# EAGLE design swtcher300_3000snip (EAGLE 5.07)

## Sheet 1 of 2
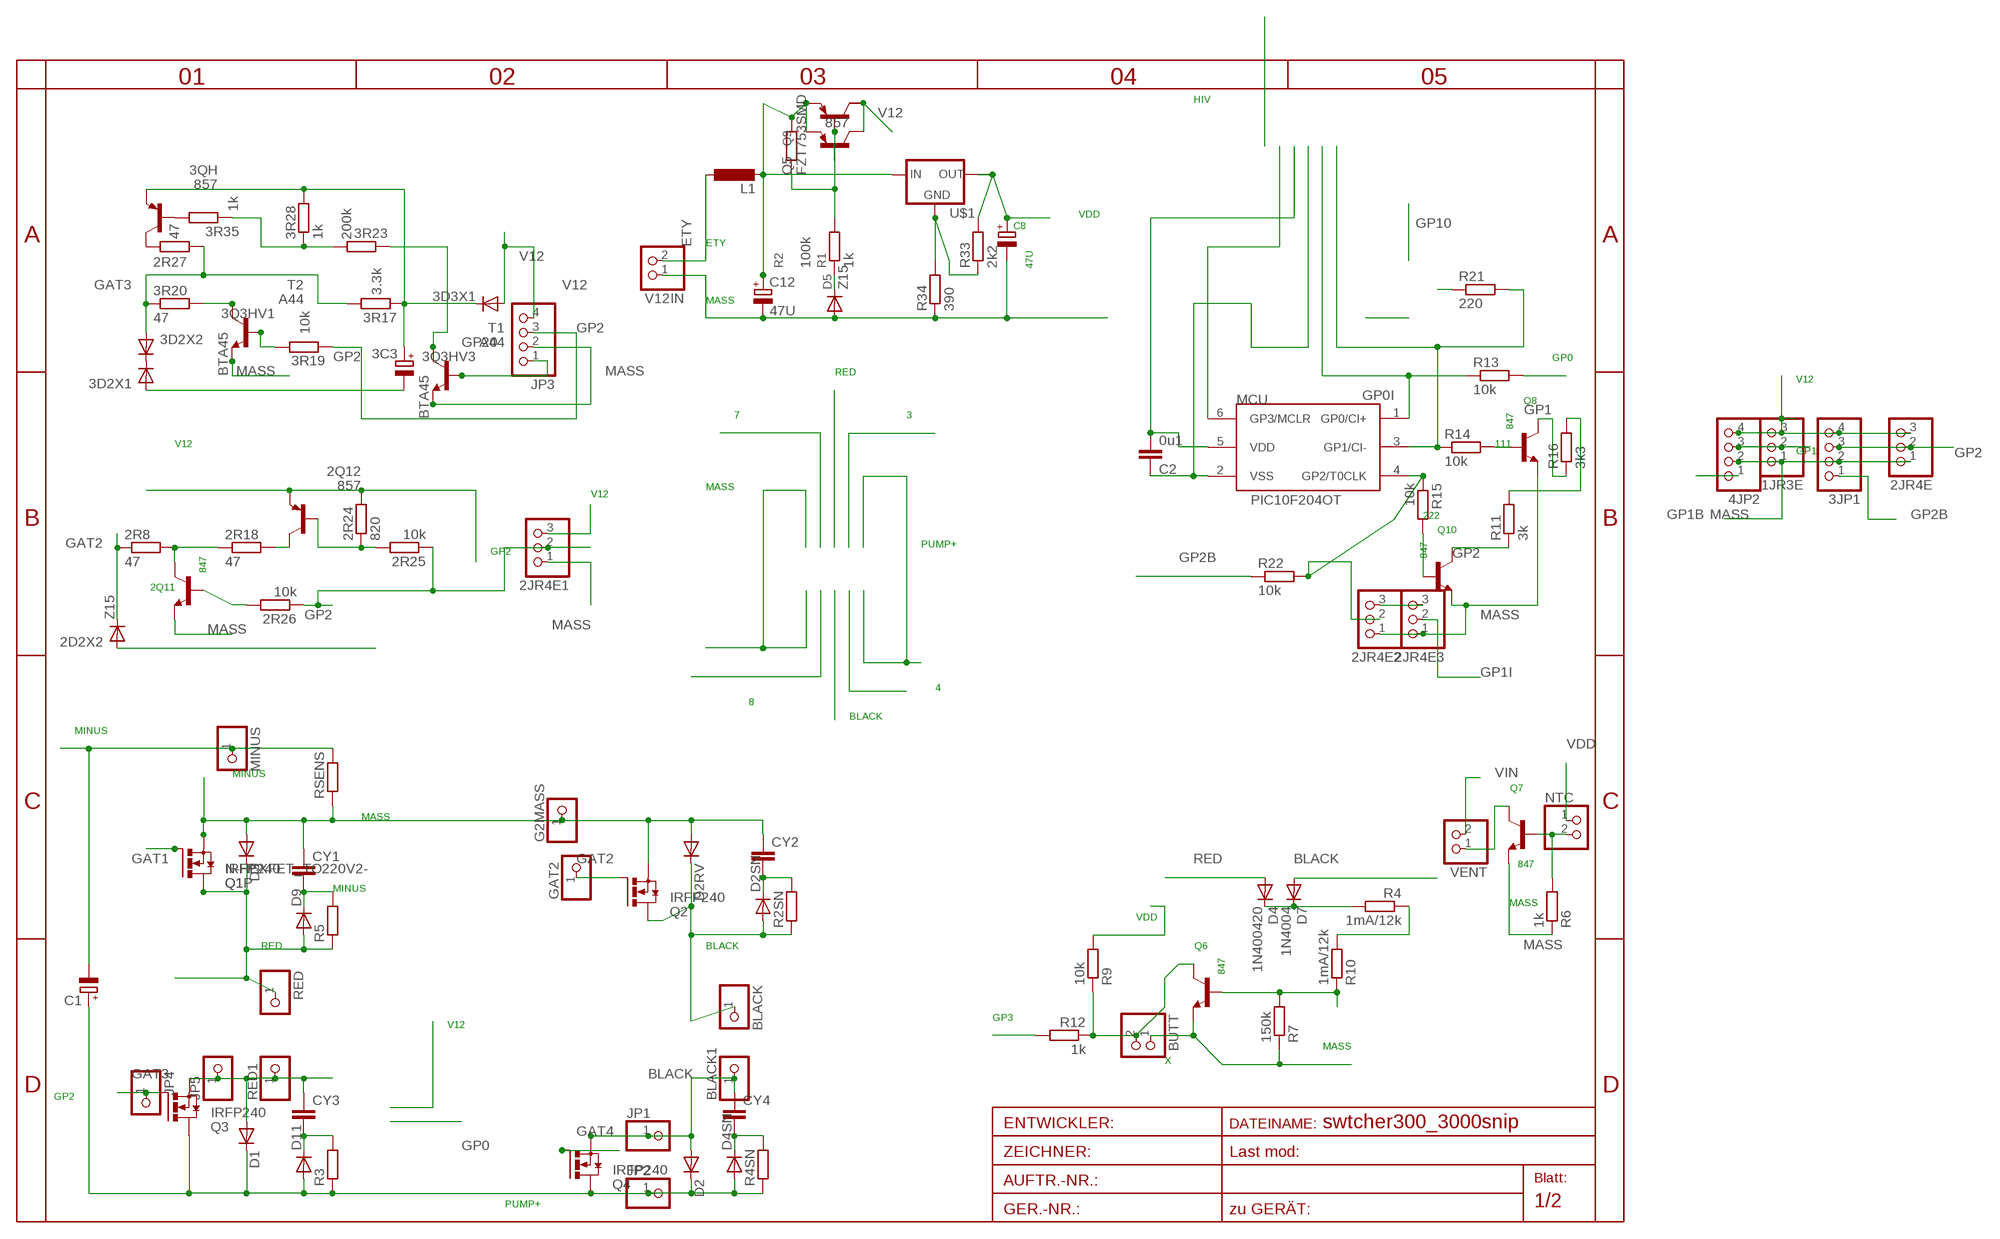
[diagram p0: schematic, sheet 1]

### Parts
1JR3E  PINHD-1X3  [1X03]
2D2X2  Z15  DIODE-MINIMELF  [MINIMELF]
2JR4E  PINHD-1X3  [1X03]
2JR4E1  PINHD-1X3  [1X03]
2JR4E2  PINHD-1X3  [1X03]
2JR4E3  PINHD-1X3  [1X03]
2Q11  847  BC847ALT1SMD  [SOT23]
2Q12  857  BC857ALT1SMD  [SOT23-BEC]
2R8  47  R-EU_R0805  [R0805]
2R18  47  R-EU_R0805  [R0805]
2R24  820  R-EU_R0805  [R0805]
2R25  10k  R-EU_R0805  [R0805]
2R26  10k  R-EU_R1206  [R1206]
2R27  47  R-EU_0207/10  [0207/10]
3C3  CPOL-EUD  [PANASONIC_D]
3D2X1  DIODE-MINIMELF  [MINIMELF]
3D2X2  DIODE-MINIMELF  [MINIMELF]
3D3X1  DIODE-SMA-DO214  [SMA-DO214AC]
3JP1  PINHD-1X4  [1X04]
3Q3HV1  BTA45  SMBTA45HV  [SOT23HV]
3Q3HV3  BTA45  SMBTA45HV  [SOT23HV]
3QH  857  BC857ALT1SMD  [SOT23-BEC]
3R17  3.3k  R-EU_R1206  [R1206]
3R19  10k  R-EU_R0805  [R0805]
3R20  47  R-EU_0207/12  [0207/12]
3R23  200k  R-EU_0204/2V  [0204V]
3R28  1k  R-EU_R0805  [R0805]
3R35  1k  R-EU_R0805  [R0805]
4JP2  PINHD-1X4  [1X04]
BLACK  PINHD-1X14.5MM  [1X4MM5]
BLACK1  PINHD-1X12MM3  [1X2MM3]
BUTT  PINHD-1X2STR  [1X02]
C1  CPOL-EUE5-13  [E5-13]
C2  0u1  C-EUC0805  [C0805]
C8  47U  CPOL-EUD  [PANASONIC_D]
C12  47U  CPOL-EUSMCA  [SMC_A]
CY1  CXXC10B6  [XC10B6]
CY2  CXXC10B6  [XC10B6]
CY3  CXXC22B7  [XC22B7]
CY4  CXXC10B5  [XC10B5]
D1  DIODE-SMC  [SMC]
D2  DIODE-SMC  [SMC]
D2RV  DIODE-SMC  [SMC]
D2SN  DIODE-SOD61E  [SOD61E]
D3  DIODE-SMC  [SMC]
D4  1N400420  [DO41-20]
D4SN  DIODE-P1-10  [P1-10]
D5  Z15  DIODE-MINIMELF  [MINIMELF]
D7  1N4004  [D-7.5]
D9  DIODE-SOD61E  [SOD61E]
D11  DIODE-D-12.5  [D-12.5]
G2MASS  PINHD-1X11MM0  [1X1MM0]
GAT2  PINHD-1X11MM0  [1X1MM0]
JP1  PINHD-1X11MM0  [1X1MM0]
JP2  PINHD-1X11MM0  [1X1MM0]
JP3  PINHD-1X4  [1X04]
JP4  PINHD-1X11MM0  [1X1MM0]
JP5  PINHD-1X11MM0  [1X1MM0]
L1  L-EU0204/5  [0204/5]
MCU  PIC10F204OT  [SOT23-6]
MINUS  PINHD-1X14.5MM  [1X4MM5]
NTC  PINHD-1X2STR  [1X02]
Q1  IRFP240  [TO247BV]
Q1P  N-HEXFET_TO220V2-  [TO220BV2]
Q2  IRFP240  [TO247BV]
Q3  IRFP240  [TO247BV]
Q4  IRFP240  [TO247BV]
Q5  FZT753SMD  [SOT223]
Q6  847  BC847ALT1SMD  [SOT23]
Q7  847  BC847ALT1SMD  [SOT23]
Q8  847  BC847ALT1SMD  [SOT23]
Q9  857  BC857ALT1SMD  [SOT23-BEC]
Q10  847  BC847ALT1SMD  [SOT23]
R1  1k  R-EU_R0805  [R0805]
R2  100k  R-EU_R0805  [R0805]
R2SN  R-EU_0617/22  [0617/22]
R3  R-EU_0617/17  [0617/17]
R4  1mA/12k  R-EU_R1210  [R1210]
R4SN  R-EU_0207/10  [0207/10]
R5  R-EU_0617/22  [0617/22]
R6  1k  R-EU_R0805  [R0805]
R7  150k  R-EU_R0805  [R0805]
R9  10k  R-EU_R0805  [R0805]
R10  1mA/12k  R-EU_R1210  [R1210]
R11  3k  R-EU_R1206  [R1206]
R12  1k  R-EU_R0805  [R0805]
R13  10k  R-EU_R0805  [R0805]
R14  10k  R-EU_R0805  [R0805]
R15  10k  R-EU_R0805  [R0805]
R16  3k3  R-EU_R0805  [R0805]
R21  220  R-EU_R0805  [R0805]
R22  10k  R-EU_R1206  [R1206]
R33  2k2  R-EU_R0805  [R0805]
R34  390  R-EU_R0805  [R0805]
RED  PINHD-1X14.5MM  [1X4MM5]
RED1  PINHD-1X12MM3  [1X2MM3]
RSENS  R-EU_CERAM35  [CERAM35]
T1  A44  2N2222-NPN-TO92-EBC  [TO92-EBC]
T2  A44  2N2222-NPN-TO92-EBC  [TO92-EBC]
U$1  AP1117  [SOT223]
V12IN  PINHD-1X2STR  [1X02]
VENT  PINHD-1X2STR  [1X02]

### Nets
111: Q8.1(B) R14.2
222: Q10.1(B) R15.2
BLACK: BLACK1.1 BLACK.1 CY4.1 D2.A D2RV.C D2SN.A D7.A JP1.1 Q2.D Q4.S R2SN.1
BTRAP+: 3C3.+ 3D3X1.K(C) 3QH.E 3R17.1 3R28.2
ETY: L1.1 V12IN.2
GAT1: Q1.G Q1P.G
GAT2: 2D2X2.C 2R8.1 GAT2.1 Q2.G
GAT3: 2R27.2 3D2X2.A 3R17.2 3R20.1 JP4.1 Q3.G
GAT4: Q4.G
GP0: R13.2
GP0I: MCU.1(GP0/CI+) R13.1 ; also sheet 2
GP1: 1JR3E.2 4JP2.3 Q8.3(C) R16.1
GP1B: 4JP2.1 R21.1
GP1I: 2JR4E3.2 MCU.3(GP1/CI-) R14.1 R21.2 ; also sheet 2
GP2: 2JR4E1.2 2JR4E.2 2R25.1 2R26.1 3JP1.3 3R19.1 JP3.3 Q10.3(C) R11.1
GP2B: 3JP1.1 3Q3HV3.1(B) JP3.1 R22.1 T1.B
GP2I: 2JR4E2.2 MCU.4(GP2/T0CLK) R15.1 R22.2 ; also sheet 2
GP3: MCU.6(GP3/MCLR) R12.2 ; also sheet 2
GP20: 3Q3HV3.3(C) 3R23.2 T1.C
HVC1: 3Q3HV1.3(C) 3R20.2 T2.C
MASS: 1JR3E.1 2D2X2.A 2JR4E1.1 2JR4E2.1 2JR4E3.1 2JR4E.1 2Q11.2(E) 3JP1.2 3Q3HV1.2(E) 3Q3HV3.2(E) 4JP2.2 BUTT.1 C2.1 C8.- C12.- CY1.1 CY2.1 D2RV.A D3.A D5.A G2MASS.1 JP3.2 MCU.2(VSS) Q1.S Q1P.S Q2.S Q6.2(E) Q7.2(E) Q8.2(E) Q10.2(E) R6.1 R7.1 R34.1 RSENS.1 T1.E T2.E V12IN.1 ; also sheet 2
MINUS: C1.- MINUS.1 RSENS.2
N$1: D4.C D7.C R4.2
N$2: Q5.1(B) Q9.B R1.2 R2.1
N$3: D5.C R1.1
N$4: 2Q11.3(C) 2R8.2 2R18.1
N$5: Q6.1(B) R7.2 R10.1
N$6: 2Q12.B 2R24.1 2R25.2
N$7: R4.1 R10.2
N$8: 2Q12.C 2R18.2
N$9: NTC.2 Q7.1(B) R6.2
N$10: Q7.3(C) VENT.1
N$12: 3Q3HV1.1(B) 3R19.2 T2.B
N$13: 2R27.1 3QH.C
N$17: 3QH.B 3R35.2
N$18: 3R23.1 3R28.1 3R35.1
N$21: 3D2X1.C 3D2X2.C
N$22: 2Q11.1(B) 2R26.2
N$30: R33.1 R34.2 U$1.1(GND)
PUMP+: C1.+ D1.C D2.C D4SN.A D11.A JP2.1 Q3.D Q4.D R3.1 R4SN.1 ; also sheet 2
RED: 3C3.- 3D2X1.A CY3.1 D1.A D3.C D4.A D9.A JP5.1 Q1.D Q1P.D Q3.S R5.1 RED1.1 RED.1
SNUB1: CY3.2 D11.C R3.2
SNUB2: CY4.2 D4SN.C R4SN.2
SNUB3: CY2.2 D2SN.C R2SN.2
SNUB4: CY1.2 D9.C R5.2
V12: 1JR3E.3 2JR4E1.3 2JR4E2.3 2JR4E3.3 2JR4E.3 2Q12.E 2R24.2 3D3X1.A 3JP1.4 4JP2.4 JP3.4 Q5.2(C) Q9.C R11.2 R16.2
VDD: C2.2 C8.+ MCU.5(VDD) NTC.1 R9.2 R33.2 U$1.2(OUT) U$1.4(TAB) ; also sheet 2
VIN: C12.+ L1.2 Q5.3(E) Q9.E R2.2 U$1.3(IN) VENT.2
X: BUTT.2 Q6.3(C) R9.1 R12.1
Unconnected: Q5.4(C/)

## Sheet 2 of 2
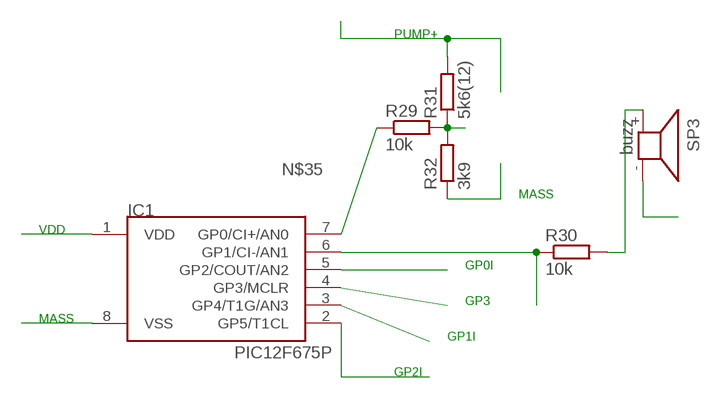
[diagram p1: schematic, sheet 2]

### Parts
IC1  PIC12F675P  [DIL8]
R29  10k  R-EU_R0805  [R0805]
R30  10k  R-EU_R0805  [R0805]
R31  5k6(12)  R-EU_0207/30  [0207/30]
R32  3k9  R-EU_R0805  [R0805]
SP3  buzz  KSS12017MM  [KSS1202]

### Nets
GP0I: IC1.5(GP2/COUT/AN2) ; also sheet 1
GP1I: IC1.3(GP4/T1G/AN3) ; also sheet 1
GP2I: IC1.2(GP5/T1CL) ; also sheet 1
GP3: IC1.4(GP3/MCLR) ; also sheet 1
MASS: IC1.8(VSS) R32.1 SP3.- ; also sheet 1
N$24: R30.2 SP3.+
N$31: IC1.6(GP1/CI-/AN1) R30.1
N$34: R29.2 R31.1 R32.2
N$35: IC1.7(GP0/CI+/AN0) R29.1
PUMP+: R31.2 ; also sheet 1
VDD: IC1.1(VDD) ; also sheet 1

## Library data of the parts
1JR3E 2JR4E 2JR4E1-2JR4E3 = pinhead:PINHD-1X3: PIN HEADER
2D2X2 3D2X1 3D2X2 3D3X1 D1 D2 D2RV D2SN D3 D4SN D5 D9 D11 = diode:DIODE-: DIODE
2Q11 Q6-Q8 Q10 = transistor-npn:BC847*: NPN Transistor
2Q12 3QH Q9 = transistor-pnp:BC857*: PNP Transistror
2R8 2R18 2R24-2R27 3R17 3R19 3R20 3R23 3R28 3R35 R2SN R4 R4SN R5-R7 R9 R10 R12 RSENS = rcl:R-EU_: RESISTOR, European symbol
3C3 C1 = rcl:CPOL-EU: POLARIZED CAPACITOR, European symbol
3JP1 4JP2 JP3 = pinhead:PINHD-1X4: PIN HEADER
3Q3HV1 3Q3HV3 = transistor-npn:SMBTA45
BLACK BLACK1 G2MASS GAT2 JP1 JP2 JP4 JP5 MINUS RED RED1 = pinhead:PINHD-1X1: PIN HEADER
BUTT NTC V12IN VENT = pinhead:PINHD-1X2: PIN HEADER
C2 = rcl:C-EU: CAPACITOR, European symbol
C8 C12 = rcl-2:CPOL-EU: POLARIZED CAPACITOR, European symbol
CY1-CY4 = rcl:CX: X CAPACITOR
D4 D7 = diode:1N4004: DIODE
IC1 = microchip-5:PIC12F6*: uPC nW 1k Program Flash memory 2x Timer Comparator 10b A/D converter/ 4xIN
L1 = rcl:L-EU: INDUCTOR, European symbol
MCU = microchip-3:PIC10F2*: uPC nW 0,25/0,5k Program Flash memory Comparator
Q1-Q4 = transistor-power:IRFP240: HEXFET Power MosFet Source: http://www.irf.com/
Q1P = transistor-power:N-HEXFET_?-*: HEXFET® Power MOSFET
Q5 = transistor-pnp:FZT753SMD: PNP Transistor
R1-R3 R11 R13-R16 R21 R22 R29-R34 = rcl-2:R-EU_: RESISTOR, European symbol
SP3 = buzzer:KSS1201: SPEAKER
T1 T2 = transistor-neu-to92:*-NPN-: NPN Transistror
U$1 = v-reg:AP1117

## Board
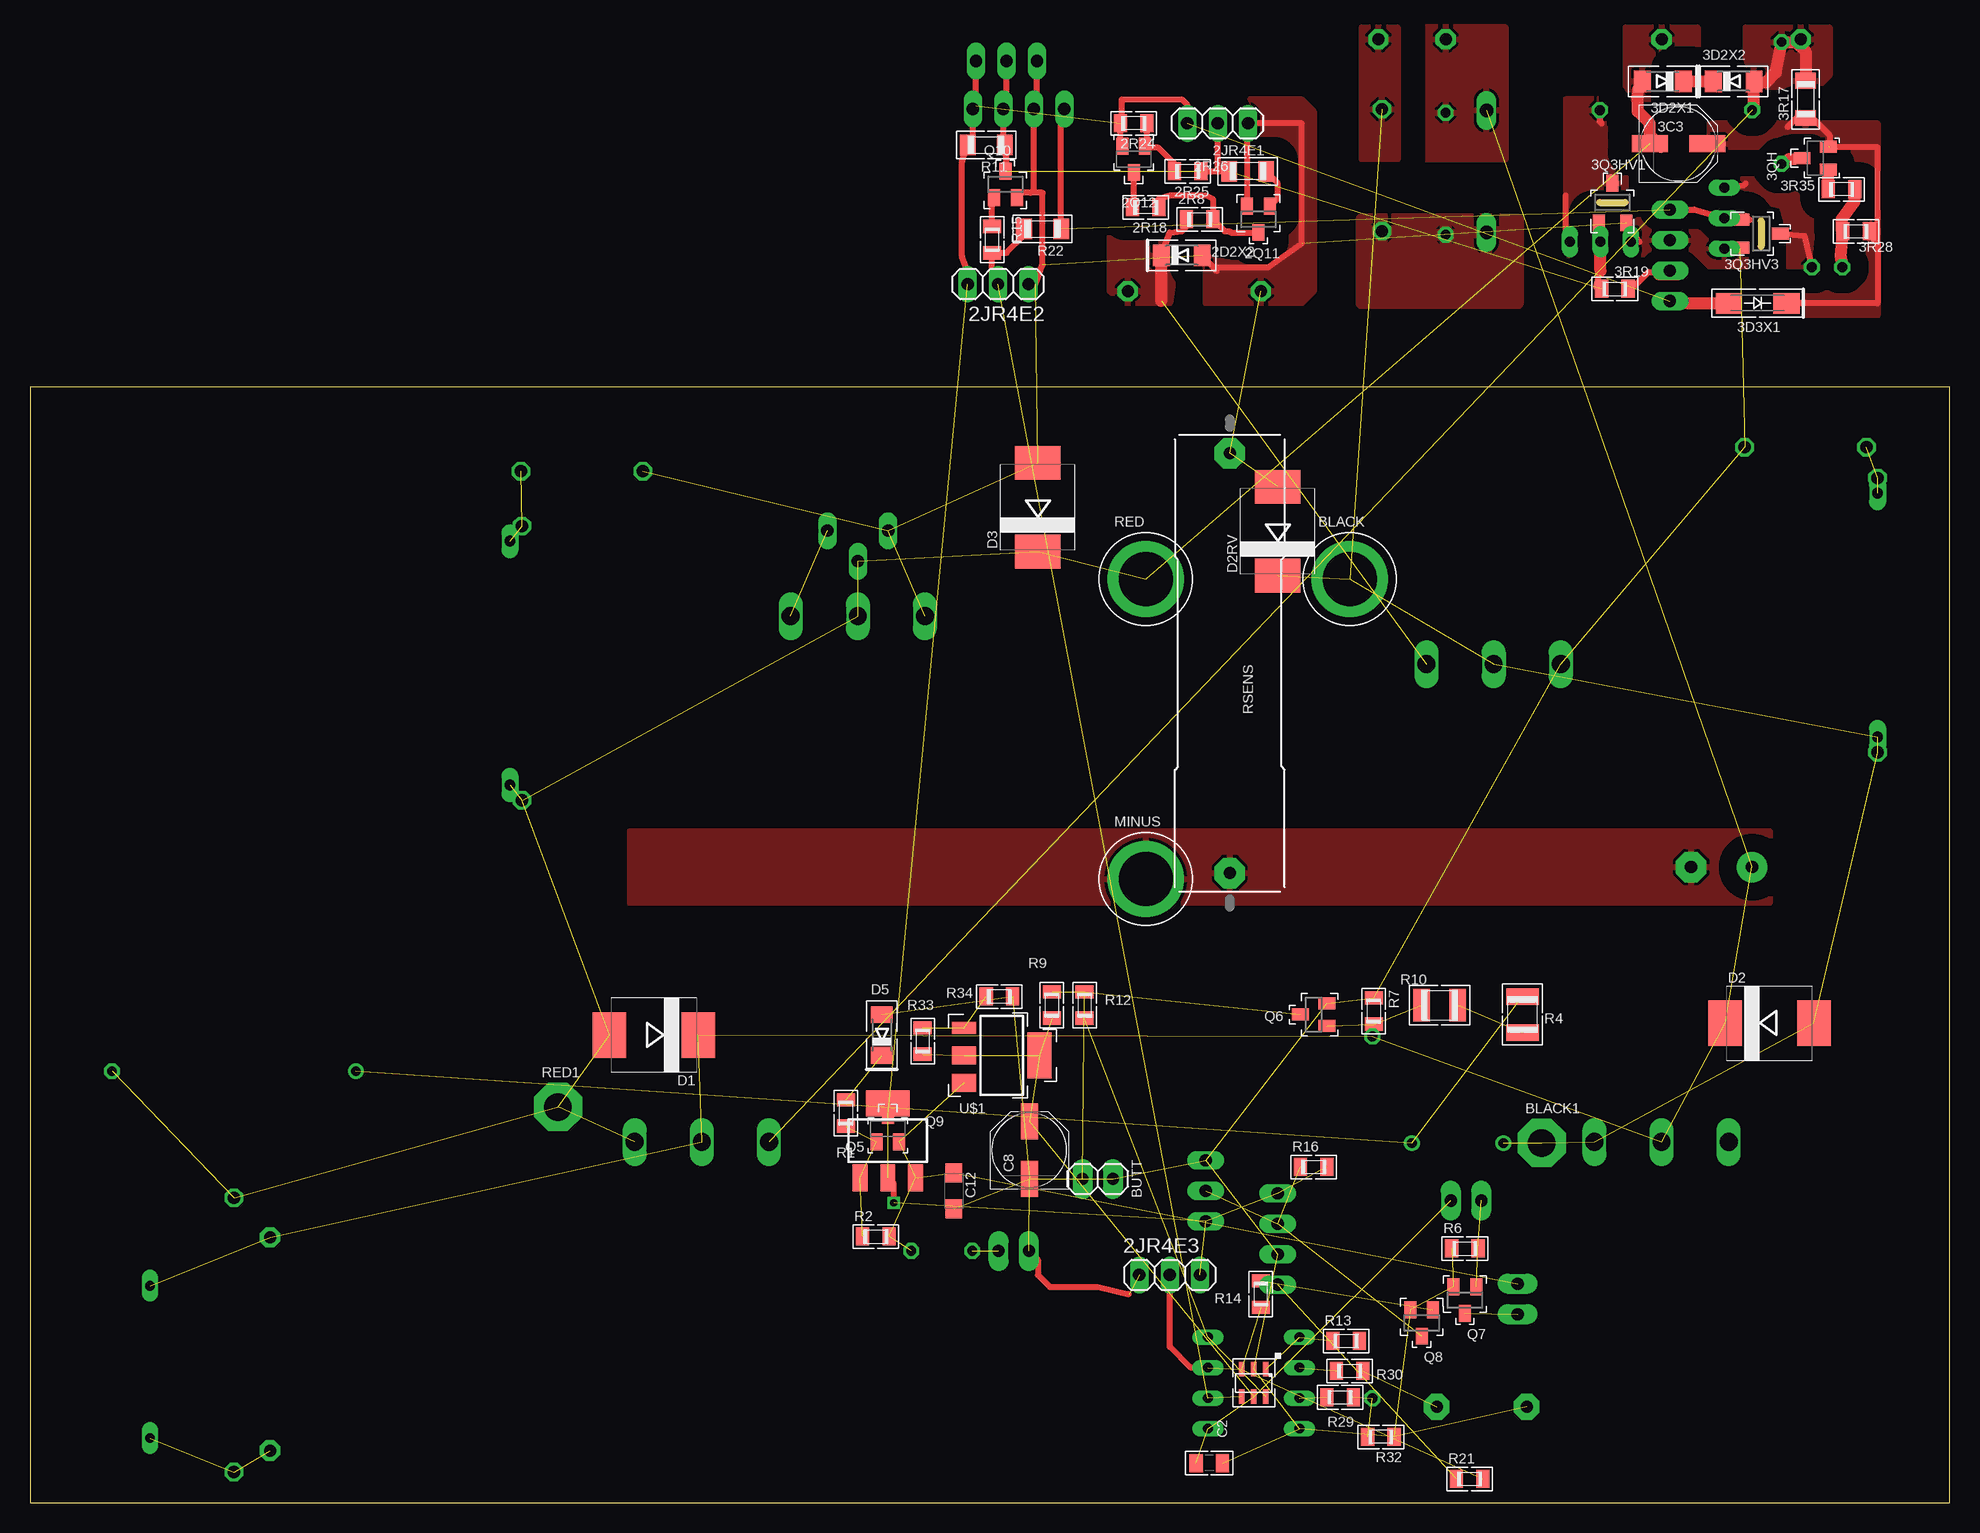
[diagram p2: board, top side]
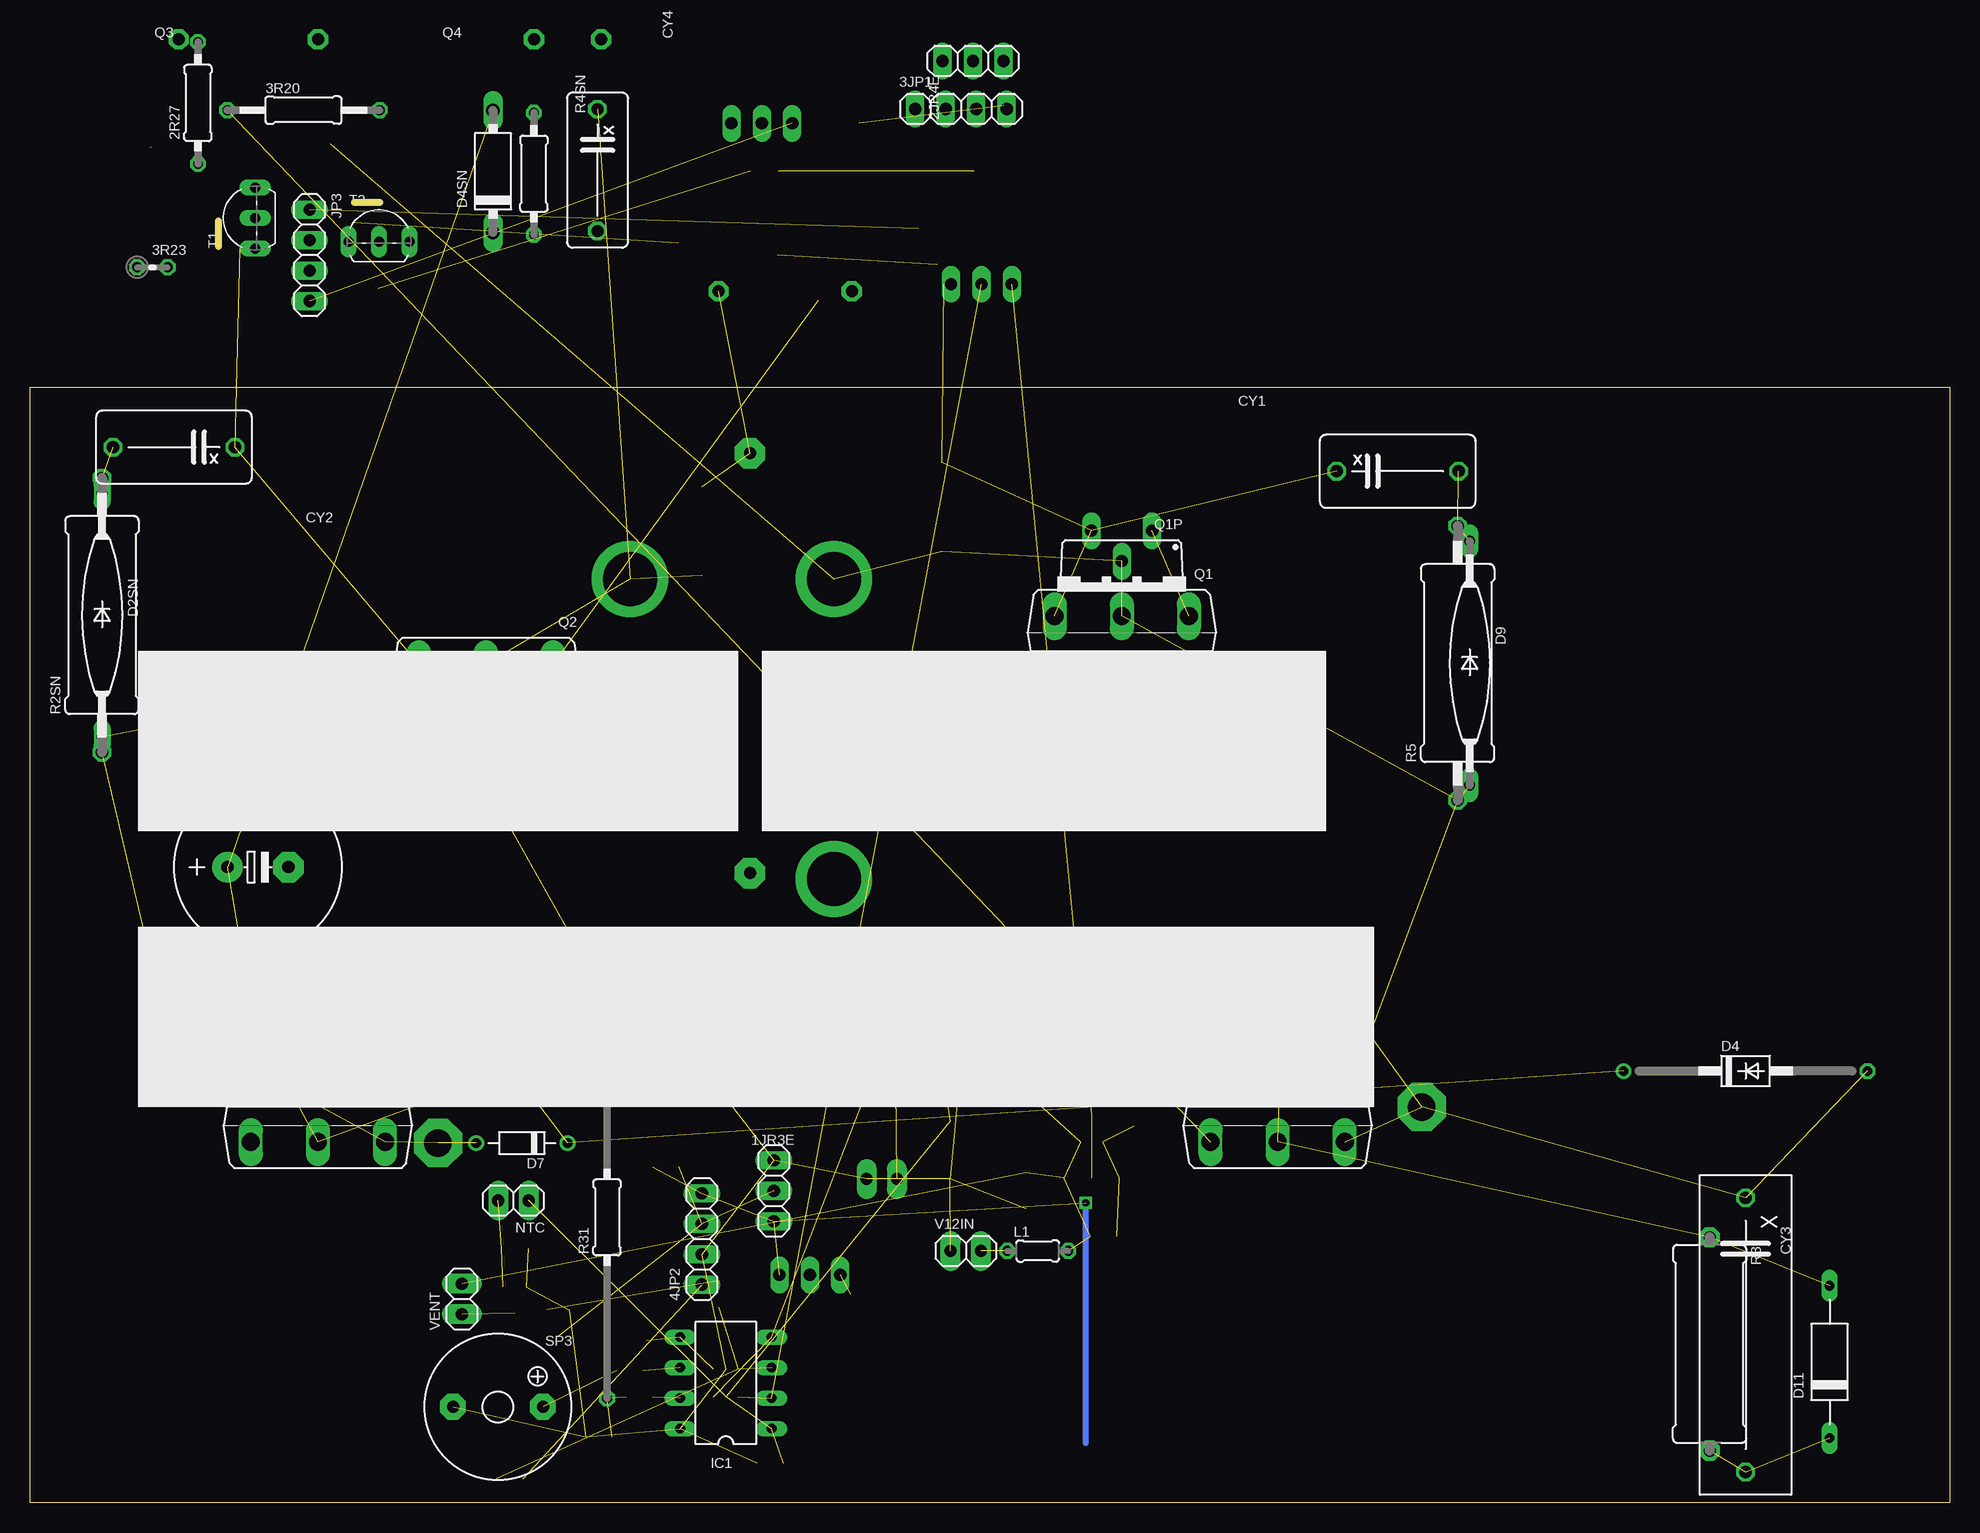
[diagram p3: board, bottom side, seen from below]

Size 160 x 93 mm. Coordinates in mm from the lower left corner, seen from the top.
Outline: 0,0 160,0 160,93 0,93 0,0
Copper layers (1*16): Top 0.035mm / dielectric 1.5mm / Bottom 0.035mm
Design rules "default *": minimum track width 10mil, minimum drill 20mil, track to track 8mil, track to pad 8mil, pad to pad 8mil, via to via 8mil, smd to smd 8mil, copper to edge 40mil, drill to drill 8mil, minimum pad ring 10mil, minimum via ring 8mil, stop-mask expansion 4mil, vias tented up to drill 0mil, thermal gap 10mil

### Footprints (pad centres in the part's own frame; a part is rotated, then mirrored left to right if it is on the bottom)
1X03 = drill 1.016 long: 1 -2.54,0; 2 0,0; 3 2.54,0
MINIMELF = smd 1.4 x 1.8: A 1.7,0; C -1.7,0
SOT23 = smd 1 x 1.4: 1 -0.95,-1.1; 2 0.95,-1.1; 3 0,1.1
SOT23-BEC = smd 1 x 1.4: B -0.95,-1.1; C 0,1.1; E 0.95,-1.1
R0805 = smd 1.1 x 1.5: 1 -1.1,0; 2 1.1,0
R1206 = smd 1.3 x 1.7: 1 -1.55,0; 2 1.55,0
0207/10 = drill 0.813 octagon: 1 -5.08,0; 2 5.08,0
PANASONIC_D = smd 3 x 1.4: + 2.4,0; - -2.4,0
SMA-DO214AC = smd 2.2 x 1.7: A 2.4,0; K -2.4,0
1X04 = drill 1.016 long: 1 -3.81,0; 2 -1.27,0; 3 1.27,0; 4 3.81,0
SOT23HV = smd 1 x 1.4: 1 -1.15,-1.7; 2 1.15,-1.7; 3 0,1.6
0207/12 = drill 0.813 octagon: 1 -6.35,0; 2 6.35,0
0204V = drill 0.813 octagon: 1 -1.27,0; 2 1.27,0
1X4MM5 = drill 4.5 pad 6.35 round: 1 0,0
1X2MM3 = drill 2.3 pad 4 octagon: 1 0,0
1X02 = drill 1.016 pad 1.676 long: 1 -1.27,0; 2 1.27,0
E5-13 = drill 1.016 pad 2.54 round: + -2.54,0 | drill 1.016 pad 2.54 octagon: - 2.54,0
C0805 = smd 1.1 x 1.5: 1 -1.1,0; 2 1.1,0
SMC_A = smd 1.6 x 1.4: + -1.5,0; - 1.5,0
XC10B6 = drill 1.016 octagon: 1 -5.08,0; 2 5.08,0
XC22B7 = drill 1.016 octagon: 1 -11.43,0; 2 11.43,0
XC10B5 = drill 1.016 octagon: 1 -5.08,0; 2 5.08,0
SMC = smd 2.8 x 3.8: A 3.7,0; C -3.7,0
SOD61E = drill 0.914 long: A 10.16,0; C -10.16,0
DO41-20 = drill 0.8 octagon: A 10.16,0 | drill 0.8 round: C -10.16,0
P1-10 = drill 1.118 long: A 5.08,0; C -5.08,0
D-7.5 = drill 0.8 round: A 3.81,0; C -3.81,0
D-12.5 = drill 0.813 long: A 6.35,0; C -6.35,0
1X1MM0 = drill 1 pad 1.676 octagon: 1 0,0
DIL8 = drill 0.8 long: 1 -3.81,-3.81; 2 -1.27,-3.81; 3 1.27,-3.81; 4 3.81,-3.81; 5 3.81,3.81; 6 1.27,3.81; 7 -1.27,3.81; 8 -3.81,3.81
0204/5 = drill 0.813 octagon: 1 -2.54,0; 2 2.54,0
SOT23-6 = smd 0.45 x 1.2: 1 -1.016,-1.15; 2 0,-1.15; 3 1.016,-1.15; 4 1.016,1.15; 5 0,1.15; 6 -1.016,1.15
TO247BV = drill 1.499 long: D 0,-2.921; G -5.588,-2.921; S 5.588,-2.921
TO220BV2 = drill 1.016 long: D 0,0; G -2.54,-2.54; S 2.54,-2.54
SOT223 = smd 1.219 x 2.235: 1 -2.311,-3.099; 2 0,-3.099; 3 2.311,-3.099 | smd 3.6 x 2.2: 4 0,3.099
0617/22 = drill 1.016 octagon: 1 -11.43,0; 2 11.43,0
0617/17 = drill 1 pad 1.676 octagon: 1 -8.89,0; 2 8.89,0
R1210 = smd 1.4 x 2.7: 1 -1.5,0; 2 1.5,0
0207/30 = drill 0.813 octagon: 1 -15.08,0; 2 15.08,0
CERAM35 = drill 1 pad 2.54 octagon: 1 -17.5,0; 2 17.5,0
KSS1202 = drill 1 pad 2.159 octagon: + 3.75,0; - -3.75,0
TO92-EBC = drill 0.813 long: B 0,-1.27; C 2.54,-1.27; E -2.54,-1.27
SOT223' = smd 1 x 2: 1 -2.3,-3.15 | smd 1.5 x 2: 2 0,-3.15; 3 2.3,-3.15 | smd 3.8 x 2: 4 0,3.15

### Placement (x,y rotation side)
1JR3E  98,26 270 bottom
2D2X2  96,104 0 top  (outside the outline)
2JR4E  81.4,120.2 0 bottom  (outside the outline)
2JR4E1  99,115 180 top  (outside the outline)
2JR4E2  80.7,101.6 180 top  (outside the outline)
2JR4E3  95,19 0 top
2Q11  102.4,107 180 top  (outside the outline)
2Q12  92,112 180 top  (outside the outline)
2R8  97.5,107 0 top  (outside the outline)
2R18  93,108 180 top  (outside the outline)
2R24  92,115 180 top  (outside the outline)
2R25  96.5,111 180 top  (outside the outline)
2R26  101.5,111 0 top  (outside the outline)
2R27  146,116.7 90 bottom  (outside the outline)
3C3  137.4,113.3 0 top  (outside the outline)
3D2X1  136.1,118.5 180 top  (outside the outline)
3D2X2  142,118.5 0 top  (outside the outline)
3D3X1  144,100 180 top  (outside the outline)
3JP1  82.4,116.2 0 bottom  (outside the outline)
3Q3HV1  131.9,108.4 0 top  (outside the outline)
3Q3HV3  144.3,105.8 270 top  (outside the outline)
3QH  148.8,112.1 90 top  (outside the outline)
3R17  148,117 90 top  (outside the outline)
3R19  not placed on the board
3R20  137.2,116.1 0 bottom  (outside the outline)
3R23  149.8,103 0 bottom  (outside the outline)
3R28  152.2,106 0 top  (outside the outline)
3R35  151,109.5 180 top  (outside the outline)
4JP2  104,22 90 bottom
BLACK  110,77 0 top
BLACK1  126,30 0 top
BUTT  89,27 180 top
C1  141,53 0 bottom
C2  98.3,3.32 180 top
C8  83.3,29.4 90 top
C12  77,26 270 top
CY1  46,86 0 bottom
CY2  148,88 180 bottom
CY3  17,14 270 bottom
CY4  not placed on the board
D1  52,39 180 top
D2  145,40 0 top
D2RV  104,81 90 top
D2SN  154,74 270 bottom
D3  84,83 90 top
D4  17,36 0 bottom
D4SN  not placed on the board
D5  71,39 90 top
D7  119,30 180 bottom
D9  40,70 270 bottom
D11  10,11.75 90 bottom
G2MASS  not placed on the board
GAT2  not placed on the board
IC1  102,10 90 bottom
JP1  not placed on the board
JP2  not placed on the board
JP3  136.7,104 270 bottom  (outside the outline)
JP4  147.6,122 0 top  (outside the outline)
JP5  not placed on the board
L1  76,21 0 bottom
MCU  102,10 180 top
MINUS  93,52 0 top
NTC  119.7,25.2 180 bottom
Q1  69,71 180 bottom
Q1P  69,78.5 180 bottom
Q2  122,67 180 bottom
Q3  56,33 0 bottom
Q4  136,33 0 bottom
Q5  71.5,30.2 0 top
Q6  107,40.7 90 top
Q7  119.6,16.9 180 top
Q8  116,15 180 top
Q9  71.5,31.2 0 top
Q10  81.3,109.9 0 top  (outside the outline)
R1  68,32.5 270 top
R2  70.5,22.2 0 top
R2SN  154,74 90 bottom
R3  20,13.25 270 bottom
R4  124.4,40.7 90 top
R4SN  not placed on the board
R5  41,70 90 bottom
R6  119.6,21.2 0 top
R7  112,41 270 top
R9  85.17,41.5 270 top
R10  117.5,41.5 0 top
R11  79.7,113.2 180 top  (outside the outline)
R12  87.9,41.5 270 top
R13  109.7,13.5 0 top
R14  102.6,17.4 90 top
R15  80.2,105.3 90 top  (outside the outline)
R16  107,28 0 top
R21  120,2 0 top
R22  84.4,106.2 180 top  (outside the outline)
R29  109.2,8.8 0 top
R30  110,11 0 top
R31  111.9,23.8 90 bottom
R32  112.6,5.5 180 top
R33  74.4,38.5 270 top
R34  80.8,42.2 180 top
RED  93,77 0 top
RED1  44,33 0 top
RSENS  100,70 270 top
SP3  121,8 0 bottom
T1  142.5,107.1 90 bottom  (outside the outline)
T2  130.9,106.4 0 bottom  (outside the outline)
U$1  AP1117  [SOT223']  81,37.3 270 top
V12IN  82,21 0 bottom
VENT  124,17 90 bottom

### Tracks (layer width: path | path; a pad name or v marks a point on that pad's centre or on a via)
111  (1 unrouted)
222
  Top 0.5: R15.2 80.2,108.85 Q10.1
BLACK  (9 unrouted)
  pour Top (isolate 2): 111,123 114,123 114,112 111,112
BTRAP+  (1 unrouted)
  Top 0.5: 3R28.2 153.3,105.7 154,105 | 154,105 154,113 150.25,113 3QH.E | 150,113 150,114 148.55,115.45 3R17.1 147.25,115.45 146.5,114.7 | 154,105 154,100 3D3X1.K
  pour Top (isolate 1.5): 140,115 154,115 154,99 147,99 147,101 152,101 152,113 140,113
ETY  (1 unrouted)
GAT1  (1 unrouted)
GAT2  (1 unrouted)
  Top 0.5: 2R8.1 96.7,106.7 96,106 95,105.9 2D2X2.C
  Top 1: 94.3,100.2 2D2X2.C
  pour Top (isolate 2): 90,106 94,106 96,107 95,100 91,100 90,101
GAT3  (1 unrouted)
  Top 0.5: 147.22,121.78 147,122 JP4.1
  Top 1: 3R20.1 143.7,116.25 3D2X2.A 144.7,118.4 145.54,119.24 2R27.2 147.22,121.78 148,121 3R17.2 | Q3.G 62,29.67
  pour Top (isolate 2): 143,123 150,123 150,119 149,118 143,118
GP0I  (2 unrouted)
GP1  (3 unrouted)
GP1B  (1 unrouted)
GP1I  (3 unrouted)
  Top 0.5: 2JR4E3.2 95,13 96.73,11.27 IC1.3
GP2  (2 unrouted)
  Top 0.5: 2R25.1 99,111 | 99,111 2R26.1 | 99,111 2JR4E1.2 | 2JR4E.2 81.4,116.47 3JP1.3 81.13,113.38 R11.1 81.35,112.25 Q10.3 | 133.2,101.2 133.5,101.2 134.9,102.6 136.57,102.6 JP3.3
  Top 1: 135.8,102.4 137.37,102.4 JP3.3
GP2B  (1 unrouted)
  Top 0.5: R22.1 85.95,115.46 3JP1.1 | T1.B 143.03,107.3 | 3Q3HV3.1 143.38,106.95 T1.B | JP3.1 138.72,107.81 T1.B
GP2I  (2 unrouted)
  Top 0.5: 2JR4E2.2 80.2,102.1 R15.1 81.4,104.2 82.85,105.65 R22.2 | IC1.2 98.16,8.7
GP3  (2 unrouted)
GP20
  Top 0.5: 3Q3HV3.3 147.9,105.63 3R23.2 | T1.C 142.84,109.84 143,110
  pour Top (isolate 1.8, rank 2): 142.1,110.4 146.1,110.4 149,107 149,103 146.6,103 146.6,106 146,108 142,109
HVC1
  Top 0.5: 3R20.2 130.85,115.15 131,115 | T2.C 128.36,105.64 128,106 128,109
  pour Top (isolate 2, rank 2): 132,117 128,117 128,104 130,104 130,107 130.9,108.4 133,109 133,115 132,116
MASS  (29 unrouted)
  Top 0.5: 3Q3HV1.2 134.15,105.12 T2.E | 98.33,103.3 98.9,102.68 | 2D2X2.A 98.33,103.3 | 2Q11.2 101.45,114.91 2JR4E1.1 106,115 106,105 103.2,103 98.64,103 98.33,103.3 | 2JR4E2.1 83.8,101.6 84.4,103.2 84.4,109.2 83.4,109.2 | 83.4,109.2 82.45,109.2 Q10.2 | 83.4,109.2 83.67,109.47 3JP1.2 83.94,116.47 2JR4E.1 | 91.6,17.4 89,18 85,18 84,19 84,20.27 V12IN.1 | T1.E 142.51,104.56 3Q3HV3.2
  pour Top (isolate 1, rank 2): 134,107 135,107 136,106 139,106 140,105 143,104.8 143,103 140,103 139,104 134,104
  pour Top (isolate 2): 101,117 106,117 107,116 107,101 106,100 98,100 98,104 100,106 100,107 101,108
MINUS
  pour Top (isolate 1.5, rank 5): 145,50 50,50 50,56 145,56
N$1  (2 unrouted)
N$2  (3 unrouted)
N$3  (1 unrouted)
N$4
  Top 0.5: 2R18.1 94.1,108.7 95,109 98,109 98.6,108.7 2R8.2 99.6,106 100,106 100.1,105.9 2Q11.3
N$5  (2 unrouted)
N$6
  Top 0.5: 2R25.2 95.5,111.5 94,113 93.05,113 2Q12.B 93.1,113.25 2R24.1
N$7  (1 unrouted)
N$8
  Top 0.5: 2Q12.C 92,108.1 2R18.2
N$9  (2 unrouted)
N$10  (1 unrouted)
N$12
  Top 0.5: 3Q3HV1.1 130.85,104.88 T2.B | 131,101.2 130.56,101.36 130.9,102.7
  Top 1: 130.9,102.7 T2.B
N$13
  Top 1: 2R27.1 146.62,112.02 3QH.C
N$17
  Top 1: 3R35.2 3QH.B
N$18
  Top 1: 3R35.1 152.1,108.5 151,107 151,106.1 3R28.1 150.9,103.97 3R23.1
N$21
  Top 1: 3D2X1.C 3D2X2.C
N$22
  Top 0.5: 2R26.2 103.05,110.95 104,110 104,108.75 2Q11.1
N$24  (1 unrouted)
N$30  (2 unrouted)
N$31  (1 unrouted)
N$34  (2 unrouted)
N$35  (1 unrouted)
PUMP+  (8 unrouted)
  pour Top (isolate 2, rank 2): 116,123 116,112 123,112 123,123
RED  (11 unrouted)
  Top 1: 3C3.- 135.95,113.05 135,114 135,115 134,116 134,117.7 3D2X1.A
  pour Top (isolate 2): 133,123 139,123 139,120 138,120 137,119 136,119 136,117 133,117
SNUB1  (2 unrouted)
SNUB2
  pour Top (isolate 2, rank 2): 111,107 124,107 124,100 111,100
SNUB3  (2 unrouted)
SNUB4  (2 unrouted)
V12  (via drill 0.6)  (8 unrouted)
  Top 0.5: 2JR4E1.3 96.46,116.54 96,117 91,117 91,115.1 2R24.2 90.9,113.25 2Q12.E | 2JR4E2.3 78.1,102.8 77.7,103.9 77.7,111.81 R11.2 78.59,113.94 3JP1.4 78.86,116.47 2JR4E.3 | v72,25 72,26.6 Q5.2
  Top 1: 3D3X1.A 138.19,100 JP3.4
  Bottom 0.5: 72,5 v72,25
VDD  (8 unrouted)
VIN  (6 unrouted)
X  (3 unrouted)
